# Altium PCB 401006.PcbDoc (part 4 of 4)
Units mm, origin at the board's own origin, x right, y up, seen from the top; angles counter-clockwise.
Board outline 117 x 63.5 mm, 4 copper layers (Top Layer, Mid-Layer 1, Mid-Layer 2, Bottom Layer), stack 1.68 mm thick; 205 components, 151 nets, 838 pads, 1570 vias.
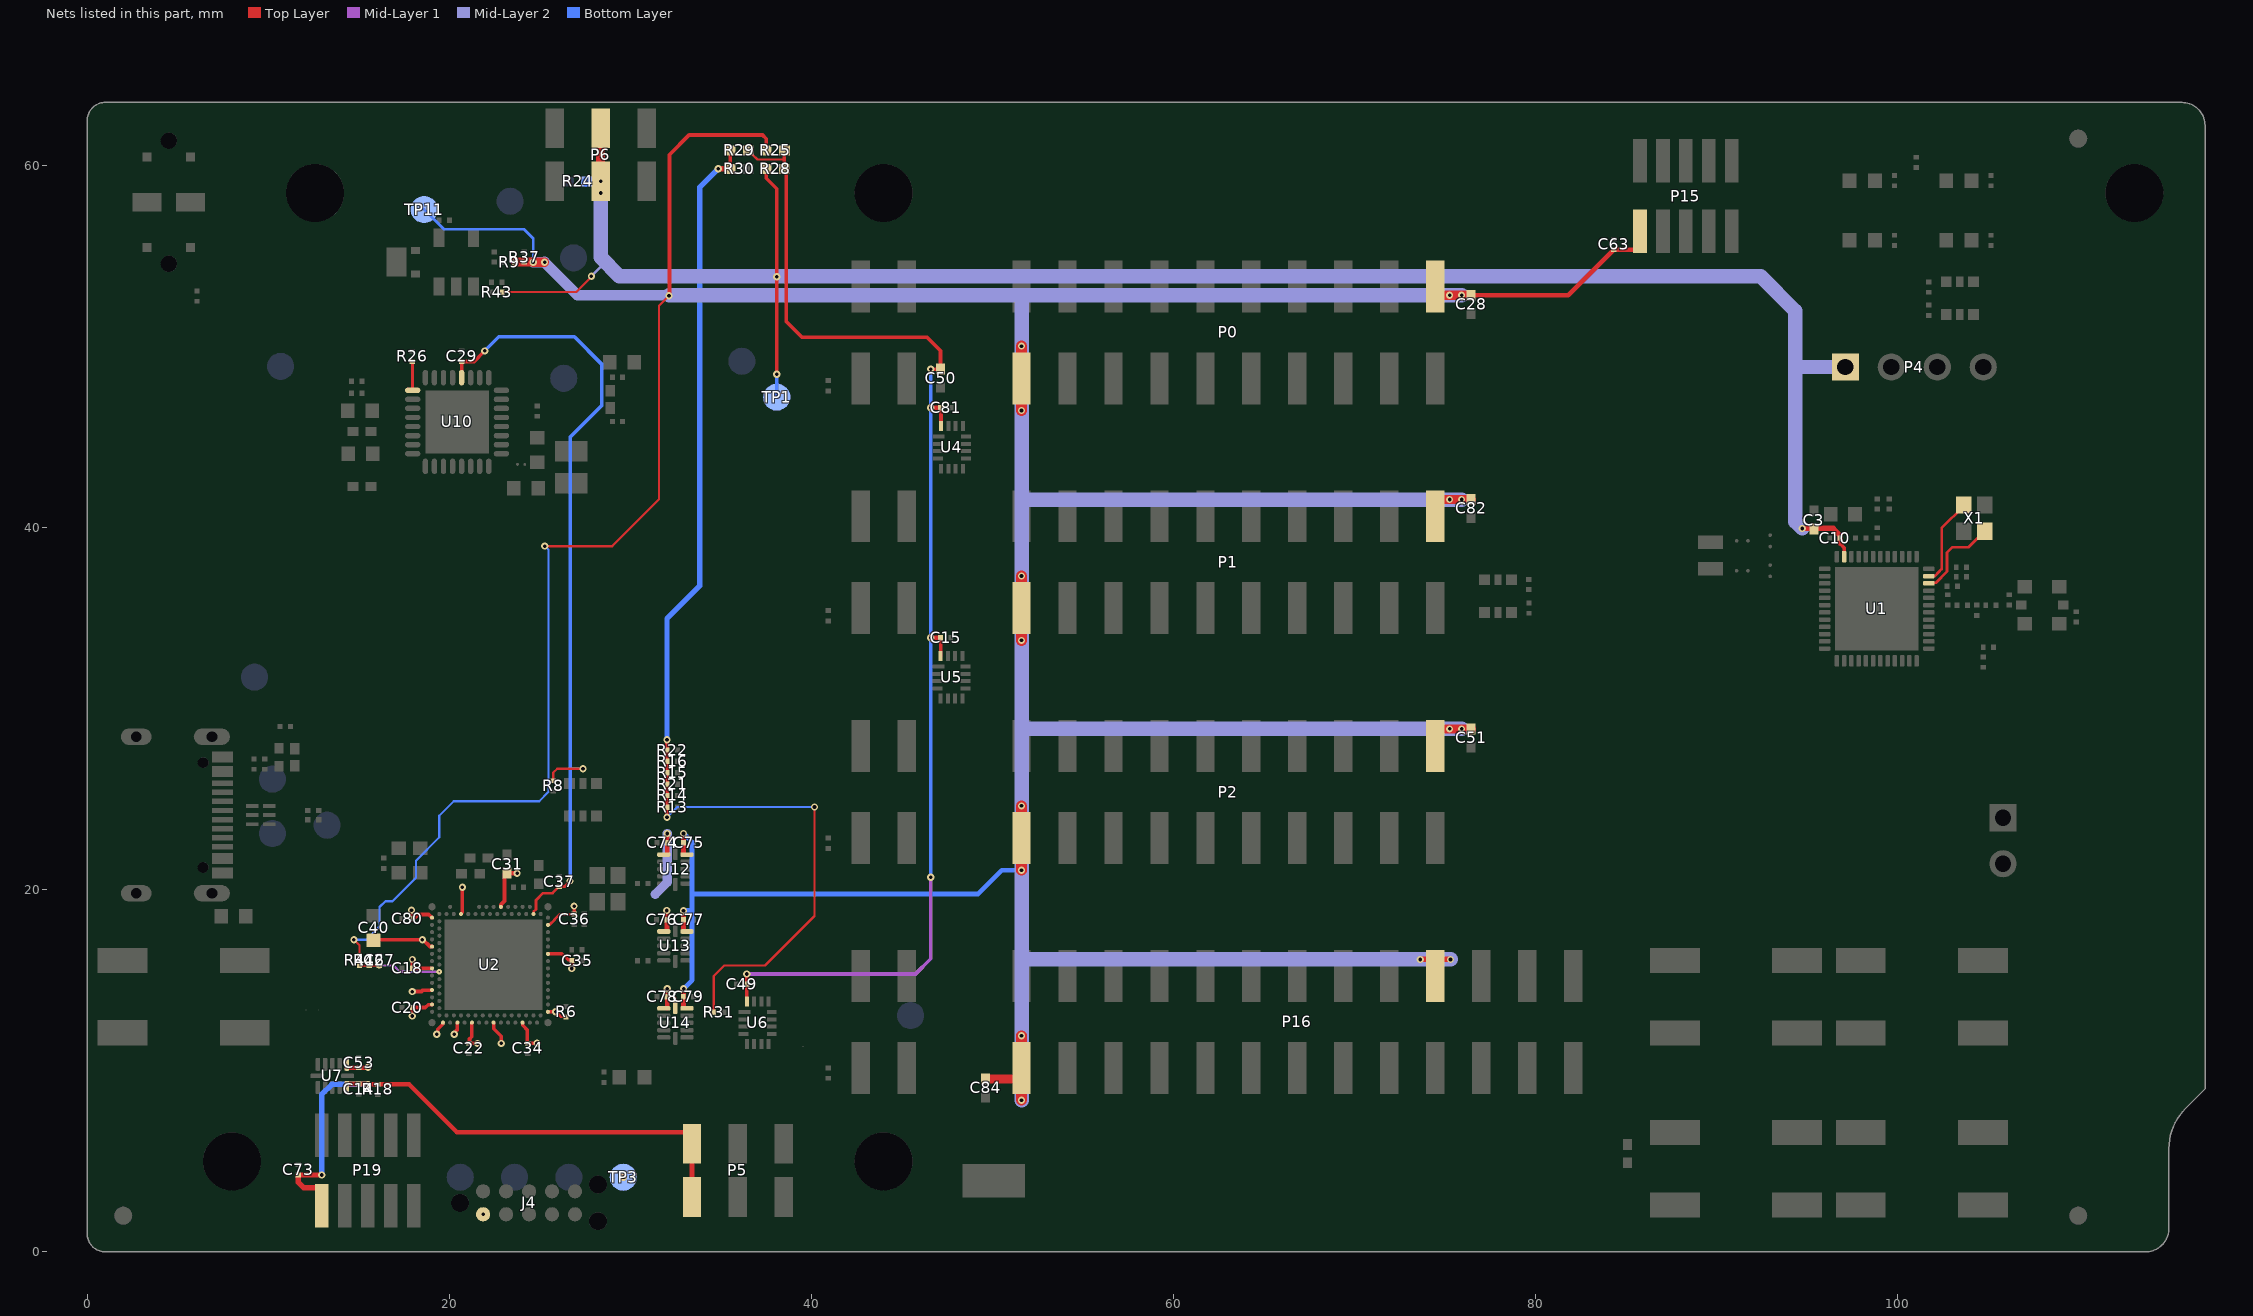
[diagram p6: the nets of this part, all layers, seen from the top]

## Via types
v1: diameter 0.4, hole 0.2, Top Layer to Bottom Layer, tented both sides, 1458 vias
v2: diameter 0.3, hole 0.1, Top Layer to Mid-Layer 1, tented top, 71 vias
v3: diameter 0.5, hole 0.25, Top Layer to Bottom Layer, tented both sides, 24 vias
v4: diameter 0.3, hole 0.1, Top Layer to Mid-Layer 1, tented both sides, 17 vias

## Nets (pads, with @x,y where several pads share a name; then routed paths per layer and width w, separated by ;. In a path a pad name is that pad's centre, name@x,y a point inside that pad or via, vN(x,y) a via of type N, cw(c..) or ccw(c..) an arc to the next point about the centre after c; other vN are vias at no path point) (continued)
VDD:DBGR: C18.1 C20.1 C22.1 C29.1 C31.1 C34.1 C35.1 C36.1 C37.1 C40.1 C53.2 C74.1 C76.1 C78.1 C80.1 J4.1 R6.2 R8.2 TP3.1 U2.A19 U2.AC1 U2.AG1 U2.AJ31 U2.AL3 U2.AL7 U2.AL11 U2.AL17 U2.AL25 U2.B8 U2.B28 U2.C1 U2.E31 U2.L1 U2.N31 U2.U1 U7.1 U10.12 U12.1 U13.1 U14.1 U14.12 | length 79.3
  Top Layer w0.125: R8.2@25.76,26.025 25.76,26.479 25.975,26.694 v1(27.4,26.694) ; C78.1@32.051,14.104 32.427,14.104 32.5,14.031 U14.12@32.5,13.5
  Top Layer w0.15: U2.B28@24.66,18.664 24.675,18.679 24.675,18.801 24.798,18.925 24.798,19.204 24.798,19.427 25.185,19.815 25.722,19.815 26.081,20.174 C37.1@26.096,20.174 26.11,20.188 26.383,20.188 v1(26.685,20.49) ; U2.E31@25.443,18.079 25.562,18.079 25.824,18.341 25.824,18.364 26.102,18.642 26.125,18.642 26.134,18.651 26.899,18.651 C36.1@26.909,18.661 ; v1(25.893,13.271) 26.173,12.991 26.454,12.991 R6.2@26.46,12.986
  Top Layer w0.187: U2.B8@20.66,18.664 20.66,18.675 20.735,18.75 v1(20.735,20.139) ; U2.N31@25.46,16.464 26.236,16.464 26.572,16.128 C35.1@26.691,16.128
  Top Layer w0.2: C40.1@16.018,17.25 v1(18.525,17.25) 18.562,17.25 18.943,16.869 19.055,16.869 U2.L1@19.06,16.864 ; v1(17.925,18.875) 17.949,18.851 17.949,18.426 C80.1@17.974,18.401 17.974,18.416 18.009,18.451 18.134,18.451 18.325,18.642 18.883,18.642 U2.C1@19.06,18.464 ; v1(17.968,13.03) 17.968,13.471 17.98,13.471 18.009,13.499 18.682,13.499 18.842,13.66 19.055,13.66 U2.AG1@19.06,13.664 ; v1(17.968,14.381) 17.976,14.388 18.481,14.388 18.558,14.464 U2.AC1@19.06,14.464 ; C18.1@17.974,15.63 v1@17.974,16.149 ; C18.1@17.979,15.664 U2.U1@19.06,15.664 ; v1(19.314,12.026) 19.372,12.083 19.372,12.296 19.655,12.58 19.655,12.66 U2.AL3@19.66,12.664 ; v1(20.279,12.026) 20.279,12.107 20.46,12.288 U2.AL7@20.46,12.664 ; U10.12@20.7,48.304 C29.1@20.7,49.19 21.39,49.19 v1(21.975,49.775) ; C22.1@21.092,11.524 21.127,11.559 21.13,11.559 21.13,11.759 21.26,11.889 U2.AL11@21.26,12.664 ; C22.1@21.101,11.521 21.572,11.521 v1(21.575,11.518) ; U2.AL17@22.46,12.664 22.46,12.334 22.878,11.916 v1(22.878,11.518) ; U2.AL25@24.06,12.664 24.065,12.66 24.065,12.514 24.318,12.261 24.318,11.549 C34.1@24.343,11.524 24.346,11.521 24.856,11.521 v1(24.86,11.525) ; U2.AJ31@25.46,13.264 25.887,13.264 v1(25.893,13.271) ; C35.1@26.691,16.128 26.748,16.128 26.783,16.093 C35.1@26.783,16.078 v1(26.782,15.659)
  Top Layer w0.203: v1(26.907,19.101) 26.909,19.1 C36.1@26.909,18.661
  Top Layer w0.225: U2.A19@22.86,19.064 22.86,19.179 23.073,19.392 23.073,20.848 C31.1@23.15,20.924 ; C31.1@23.2,20.916 v1(23.759,20.916)
  Top Layer w0.27: U7.1@14.362,10.174 C53.2@15.004,10.174 15.499,10.174 v1(15.525,10.2) ; U13.1@32.031,17.737 C76.1@32.031,18.354 v1(32.031,18.862) ; U14.1@32.051,13.462 32.051,14.104 v1(32.051,14.539) ; U12.1@32.051,21.987 C74.1@32.051,22.604 v1(32.051,23.112)
  Mid-Layer 1 w0.2: v1@21.541,11.484 v1(21.575,11.518) v1@21.632,11.461
  Mid-Layer 2 w0.508: 31.39,19.759 32.051,20.42 v1(32.051,23.112)
  Bottom Layer w0.125: 26.685,26.694 v1(27.4,26.694)
  Bottom Layer w0.2: v1(21.575,11.518) v1@21.656,11.518 ; v1(21.975,49.775) 22.75,50.55 26.925,50.55 28.425,49.05 28.425,46.739 26.685,44.999 26.685,26.694 v1(26.685,20.49)
  other v1: 21.878,2.074 29.62,4.125 17.975,16.15
VDD:IO: C28.2 C51.2 C63.2 C75.1 C77.1 C79.1 C82.2 C84.2 P0.1 P0.20 P1.1 P1.20 P2.1 P2.20 P15.1 P16.1 P16.20 R9.2 R25.1 R37.2 R41.2 TP11.1 U12.11 U13.11 U14.11 | length 311.3
  Top Layer w0.125: v1(14.742,17.25) 15.053,16.939 R41.2@15.053,16.384 ; v1(25.288,38.989) 29.014,38.989 31.598,41.572 31.598,52.273 v1(32.15,52.825)
  Top Layer w0.2: R37.2@24.142,54.675 R37.2@24.144,54.672 ; v1@24.647,54.672 v1(24.65,54.67) ; v1(32.15,52.825) 32.175,52.85 32.175,60.615 33.26,61.7 37.318,61.7 37.525,61.493 R25.1@37.525,60.85
  Top Layer w0.25: C28.2@76.466,52.845 81.821,52.845 C63.2@84.346,55.37 85.784,55.37 P15.1@85.784,56.38
  Top Layer w0.27: U14.11@32.948,13.514 32.952,14.104 v1(32.955,14.539) C79.1@32.948,14.104 ; U13.11@32.948,17.727 C77.1@32.948,18.344 v1(32.948,18.852) ; U12.11@32.948,21.987 C75.1@32.948,22.604 v1(32.948,23.112)
  Top Layer w0.305: v1(73.646,16.156) v1(75.322,16.156)
  Top Layer w0.5: R9.2@23.669,54.674 R37.2@24.142,54.675 24.645,54.674 v1@24.647,54.672 ; v1@24.652,54.672 v1(25.278,54.672)
  Top Layer w0.508: C84.2@49.643,9.556 51.37,9.556 51.624,9.81 P16.1@51.624,10.16 ; P2.20@74.484,27.94 74.484,28.639 74.738,28.893 v1(75.272,28.893) v1(75.934,28.893) C51.2@76.466,28.893 ; P1.20@74.484,40.64 74.484,41.314 74.738,41.568 v1(75.272,41.568) v1(75.934,41.568) C82.2@76.466,41.568 ; P0.20@74.484,53.34 74.484,53.099 74.738,52.845 v1(75.272,52.845) v1(75.934,52.845) C28.2@76.466,52.845
  Top Layer w0.6: v1(51.624,8.382) P16.1@51.624,9.81 ; P16.1@51.624,10.16 v1(51.624,11.938) ; v1(51.624,21.082) P2.1@51.624,22.86 v1(51.624,24.638) ; v1(51.624,33.782) P1.1@51.624,35.56 v1(51.624,37.338) ; v1(51.624,46.482) P0.1@51.624,48.26 v1(51.624,50.038)
  Mid-Layer 2 w0.6: v1(24.65,54.67) 24.652,54.672 v1(25.278,54.672) ; v1@25.275,54.675 v1(25.278,54.672) ; v1@32.125,52.85 27.1,52.85 v1(25.278,54.672)
  Mid-Layer 2 w0.8: v1@32.17,52.845 51.624,52.845 ; v1(51.624,8.382) 51.624,16.162 ; 51.65,28.905 75.272,28.905 v1@75.934,28.905 ; v1(75.322,16.156) v1(73.646,16.156) 51.631,16.156 51.624,16.162 ; v1@75.934,41.561 51.624,41.561 ; v1(75.934,52.845) v1(75.272,52.845) 51.624,52.845 ; 51.624,16.162 v1(51.624,24.638) 51.624,28.905 v1(51.624,33.782) v1(51.624,37.338) 51.624,41.561 ; 51.624,41.561 v1(51.624,46.482) v1(51.624,50.038) 51.624,52.845
  Bottom Layer w0.125: v1(14.742,17.25) 15.438,17.25 16.162,17.974 16.162,19.049 16.488,19.375 16.875,19.375 18.175,20.675 18.175,21.614 19.462,22.901 19.462,24.098 20.264,24.9 24.975,24.9 25.487,25.413 25.487,38.789 v1(25.288,38.989)
  Bottom Layer w0.15: TP11.1@18.622,57.582 19.704,56.5 24.127,56.5 24.65,55.977 v1(24.65,54.67)
  Bottom Layer w0.27: v1(32.948,18.852) 33.423,18.852 ; v1(32.948,23.112) 33.423,22.636 33.423,19.775 ; v1(32.955,14.539) 33.423,15.007 33.423,18.852 ; v1(51.624,21.082) 50.532,21.082 49.225,19.775 33.423,19.775 ; 33.423,18.852 33.423,19.775
VDD:nRF: C3.2 C10.1 P4.1 P6.2 R24.1 R28.1 R43.1 TP1.1 U1.47 | length 114.1
  Top Layer w0.125: R43.1@22.92,53.025 27.025,53.025 v1@27.894,53.894
  Top Layer w0.2: R28.1@37.519,59.83 37.519,59.31 38.104,58.725 v1(38.104,53.863) v1(38.104,48.489) ; 96.873,39.142 96.873,39.085 97.068,38.889 U1.47@97.068,38.555
  Top Layer w0.3: v1(28.372,58.493) v1(28.372,59.141) ; v1(94.756,39.966) 96.458,39.966 96.844,39.58 C10.1@96.844,39.438 96.844,39.17 96.873,39.142
  Top Layer w0.5: v1(28.372,59.141) P6.2@28.372,62.071
  Mid-Layer 2 w0.15: v1(27.862,53.9) 28.372,54.41 28.372,54.937
  Mid-Layer 2 w0.8: v1(28.372,59.141) v1(28.372,58.493) 28.372,54.937 29.409,53.9 31.65,53.9 ; 31.7,53.9 92.455,53.9 94.375,51.98 94.375,48.884 ; v1(94.756,39.966) 94.375,40.347 94.375,48.884 ; P4.1@97.134,48.884 94.375,48.884
  Bottom Layer w0.2: TP1.1@38.104,47.219 v1(38.104,48.489)
  Bottom Layer w0.55: R24.1@27.599,59.141 v1(28.372,59.141) v1(28.372,58.493)
VDD:SW: C15.1 C49.1 C50.2 C81.1 R25.2 R28.2 R29.2 U4.16 U5.16 U6.16 | length 70.4
  Top Layer w0.125: R29.2@36.525,60.85 36.55,60.85 36.762,60.637 36.762,60.612 37.034,60.341 38.519,60.341 ; R25.2@38.287,60.637 38.5,60.85 R25.2@38.525,60.85
  Top Layer w0.2: U6.16@36.45,13.825 C49.1@36.45,14.794 v1(36.45,15.35) ; R28.2@38.519,59.83 38.519,60.341 R25.2@38.519,60.836 ; R28.2@38.625,59.83 38.625,51.397 39.497,50.525 46.4,50.525 47.15,49.775 C50.2@47.15,48.769 v1(46.615,48.769) ; C15.1@47.154,33.917 47.16,33.911 U5.16@47.16,32.911 ; U4.16@47.178,45.612 C81.1@47.178,46.628
  Top Layer w0.254: v1(46.609,33.928) C15.1@47.143,33.928 ; v1(46.615,46.628) C81.1@47.148,46.628
  Mid-Layer 1 w0.2: v1(36.45,15.35) 45.766,15.35 46.615,16.199 v1(46.615,20.695)
  Bottom Layer w0.2: v1(46.615,20.695) v1(46.615,46.628) v1(46.615,48.769)
VDD:SW_PU: R13.1 R14.1 R15.1 R16.1 R21.1 R22.1 R29.1 R30.1 R31.1 | length 62
  Top Layer w0.125: R31.1@34.621,13.25 34.621,15.241 35.2,15.821 37.454,15.821 40.189,18.556 v1(40.189,24.575)
  Top Layer w0.2: v1(32.04,24.006) R13.1@32.04,24.575 R14.1@32.04,25.214 R15.1@32.04,26.47 R22.1@32.04,27.726 v1(32.04,28.295) ; R30.1@35.525,59.83 R29.1@35.525,60.85
  Top Layer w0.3: v1(34.865,59.83) R30.1@35.525,59.83
  Bottom Layer w0.125: v1(32.04,24.006) 32.609,24.575 v1(40.189,24.575)
  Bottom Layer w0.3: v1(32.04,28.295) 32.04,34.987 33.84,36.787 33.84,58.805 v1(34.865,59.83)
VDD:SWD0: C14.1 C73.2 P5.3 P19.1 R18.2 U7.11 | length 34.7
  Top Layer w0.15: v1(15.525,9.25) v1@15.531,9.256 ; R18.2@16.058,9.256 R18.2@16.064,9.262
  Top Layer w0.25: v1(15.525,9.25) 16.058,9.25 17.8,9.25 20.433,6.616 33.035,6.616 33.42,6.231 P5.3@33.42,3.035
  Top Layer w0.27: U7.11@14.411,9.275 14.414,9.277 C14.1@15.004,9.277 15.498,9.277 v1(15.525,9.25)
  Top Layer w0.3: P19.1@12.964,2.55 12.964,3.32 12.734,3.55 11.964,3.55 11.679,3.835 C73.2@11.679,4.246 v1(12.964,4.246)
  Bottom Layer w0.3: v1(12.964,4.246) 12.964,8.689 13.525,9.25 v1(15.525,9.25)
VMEAS_CH1: C67.1 R41.1 R42.2 U2.V2 | length 4.5
  Top Layer w0.125: R41.1@15.053,15.814 16.143,15.814 v2(16.145,15.815)
  Mid-Layer 1 w0.125: v2(16.145,15.815) 16.935,15.815 17.27,15.48 v2(19.46,15.48)
VSET1: R26.1 U10.17 | length 1.9
  Top Layer w0.15: U10.17@17.742,47.665 17.811,47.596 U10.17@17.992,47.596 17.974,47.614 R26.1@17.974,49.183
XC1: U1.34 X1.1 | length 4.9
  Top Layer w0.15: U1.34@101.698,36.93 101.735,36.967 102.138,36.967 102.755,37.583 102.755,38.63 103.055,38.93 103.951,38.93 X1.1@104.83,39.809
XC2: U1.35 X1.3 | length 5
  Top Layer w0.15: U1.35@101.698,37.33 U1.35@101.748,37.38 ; U1.35@101.748,37.33 102.075,37.33 102.293,37.549 102.293,37.552 102.455,37.714 102.455,39.984 103.68,41.209 X1.3@103.68,41.259
pads on no net: Fid1.0 Fid2.0 Fid3.0 H1. H2. H3. H4. H5. J3. J3.0 J3.A8 J3.B8 J4.0 J4.6 J4.7 J4.8 J4.9 P0.8 P0.9 P0.10 P0.11 P0.12 P0.13 P0.14 P0.15 P0.16 P0.17 P0.18 P5.2 P15.6 P15.7 P15.8 P16.21 P16.22 P16.23 P16.24 P16.25 P16.26 P17.3 P19.7 P19.8 P19.9 P30.3 P31.3 P32.3 SW4.0 SW4.1 SW4.6 U2. U2.A1 U2.A21 U2.A31 U2.AD2 U2.AE31 U2.AG31 U2.AH2 U2.AJ1 U2.AK2 U2.AK4 U2.AK6 U2.AK8 U2.AK10 U2.AK12 U2.AK14 U2.AK22 U2.AK24 U2.AK26 U2.AK28 U2.AK30 U2.AL1 U2.AL31 U2.B10 U2.B14 U2.D2 U2.F2 U2.J1 U2.K2 U2.M2 U2.P2 U2.T2 U2.W1 U2.Y2 U4.7 U4.12 U5.7 U5.12 U6.7 U6.12 U6.13 U6.14 U6.15 U10.5 U10.7 U10.9 U10.10 U10.11 U10.15 U10.18 U10.19 U10.25 U10.26 U10.27 U14.2 U14.10

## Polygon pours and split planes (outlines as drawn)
GND on Top Layer "Top_Layer-GND" (solid, remove dead copper, pour order 10): 0.002,0.009 0.002,63.509 117.004,63.509 117.004,0.009
P5V0 on Top Layer "P5V0" (solid, remove dead copper, pour order 0): 16.496,48.5 16.496,50.01 17.748,51.263 17.748,59.646 17.294,60.1 14.15,60.1 10.475,56.425 10.475,49.451 11.426,48.5
GND on Top Layer "GND_island" (solid, pour order 4): 103.874,35.423 103.874,34.914 104.306,34.482 104.991,34.482 105.397,34.888 105.397,35.422
GND on Mid-Layer 2 "Mid_Layer2-GND" (solid, remove dead copper, pour order 7): 0.029,0 0.029,63.5 117.004,63.5 117.004,0
VDD:DBGR on Mid-Layer 2 "VDD_DBGR" (solid, pour order 6): 21.754,1.825 25.2,1.825 26.025,2.65 29.176,2.65 30.011,3.485 30.011,4.789 28.85,5.95 28.85,10.719 32.51,14.379 32.51,19.319 30.379,21.45 19,21.45 17.725,20.175 17.725,14.809 15.02,12.104 15.02,10.019 21.219,3.821 21.219,2.36
GND on Mid-Layer 1 "Mid_Layer1-GND" (solid, remove dead copper, pour order 1): 0.029,0 0.029,63.22 117.004,63.22 117.004,0
GND on Bottom Layer "Bottom_Layer-GND" (solid, remove dead copper, pour order 3): 0.029,0 0.029,63.5 117.004,63.5 117.004,0

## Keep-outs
Top Layer:
  region: 112,26.473 cw(c112,29.973) 108.5,29.973 cw(c112,29.973) 112,33.473 cw(c112,29.973) 115.5,29.973 cw(c112,29.973)
  region: 108.496,6.473 cw(c108.496,9.973) 104.996,9.973 cw(c108.496,9.973) 108.496,13.473 cw(c108.496,9.973) 111.996,9.973 cw(c108.496,9.973)
  region: 42.496,14.473 cw(c42.496,17.973) 38.996,17.973 cw(c42.496,17.973) 42.496,21.473 cw(c42.496,17.973) 45.996,17.973 cw(c42.496,17.973)
  region: 74.996,0.473 cw(c74.996,3.973) 71.496,3.973 cw(c74.996,3.973) 74.996,7.473 cw(c74.996,3.973) 78.496,3.973 cw(c74.996,3.973)
  region: 3.496,-0.027 cw(c3.496,3.473) -0.004,3.473 cw(c3.496,3.473) 3.496,6.973 cw(c3.496,3.473) 6.996,3.473 cw(c3.496,3.473)
  region: 20.496,33.473 cw(c20.496,36.973) 16.996,36.973 cw(c20.496,36.973) 20.496,40.473 cw(c20.496,36.973) 23.996,36.973 cw(c20.496,36.973)
  region: 16.496,56.973 cw(c16.496,60.473) 12.996,60.473 cw(c16.496,60.473) 16.496,63.973 cw(c16.496,60.473) 19.996,60.473 cw(c16.496,60.473)
  region: 35.496,52.473 cw(c35.496,55.973) 31.996,55.973 cw(c35.496,55.973) 35.496,59.473 cw(c35.496,55.973) 38.996,55.973 cw(c35.496,55.973)
  region: 77.796,54.973 cw(c77.796,58.473) 74.296,58.473 cw(c77.796,58.473) 77.796,61.973 cw(c77.796,58.473) 81.296,58.473 cw(c77.796,58.473)
  region: 46.352,19.687 ccw(c49.352,19.687) 49.352,16.687 ccw(c49.352,19.687) 52.352,19.687 ccw(c49.352,19.687) 49.352,22.687 ccw(c49.352,19.687)
  region: 8.004,2 cw(c8.004,5) 5.004,5 cw(c8.004,5) 8.004,8 cw(c8.004,5) 11.004,5 cw(c8.004,5)
  region: 44.004,2 cw(c44.004,5) 41.004,5 cw(c44.004,5) 44.004,8 cw(c44.004,5) 47.004,5 cw(c44.004,5)
  region: 106.004,1.979 cw(c106.004,4.979) 103.004,4.979 cw(c106.004,4.979) 106.004,7.979 cw(c106.004,4.979) 109.004,4.979 cw(c106.004,4.979)
  region: 98.967,25.576 cw(c98.967,28.576) 95.967,28.576 cw(c98.967,28.576) 98.967,31.576 cw(c98.967,28.576) 101.967,28.576 cw(c98.967,28.576)
  region: 113.104,55.5 cw(c113.104,58.5) 110.104,58.5 cw(c113.104,58.5) 113.104,61.5 cw(c113.104,58.5) 116.104,58.5 cw(c113.104,58.5)
  region: 44.004,55.5 cw(c44.004,58.5) 41.004,58.5 cw(c44.004,58.5) 44.004,61.5 cw(c44.004,58.5) 47.004,58.5 cw(c44.004,58.5)
  region: 16.439,59.569 cw(c16.439,62.569) 13.439,62.569 cw(c16.439,62.569) 16.439,65.569 cw(c16.439,62.569) 19.439,62.569 cw(c16.439,62.569)
Keep-Out Layer:
  circle w0.152: c12.604,58.5 r2.4
  circle w0.152: c113.104,58.5 r2.4
  circle w0.152: c113.104,58.5 r2.4
  circle w0.152: c44.004,5 r2.4
  circle w0.152: c44.004,58.5 r2.4
  circle w0.152: c8.004,5 r2.4

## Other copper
Top Layer:
  rectangle net GND: 6.891,20.422 8.776,21.247
  rectangle net GND: 6.919,27.025 8.804,27.85
  rectangle net GND: 109.224,34.036 110.038,34.931
  rectangle net PCBANT: 115.025,16.986 116.295,17.748
  pour cut-out: 19.46,18.664 25.46,18.664 25.46,13.064 19.46,13.064
  pour cut-out: 18.4,47.9 22.5,47.9 22.5,43.8 18.4,43.8
  pour cut-out: 96.038,38.3 101.588,38.3 101.588,32.7 96.038,32.7
  pour cut-out: 59.075,26.354 57.866,26.354 57.866,26.875 59.075,26.875
  pour cut-out: 56.686,24.808 56.686,26.018 56.876,26.018 56.876,24.808
  pour cut-out: 54.821,29.737 57.983,29.737 57.983,29.216 54.821,29.216
  pour cut-out: 88.839,38.697 88.839,36.825 88.872,36.825 88.872,38.697
  region net RF: 106.555,35.98 106.35,35.865 106.35,35.595 106.555,35.48
  pour cut-out: 103.186,37.196 103.186,35.986 102.665,35.986 102.665,37.196
  pour cut-out: 103.615,35.429 103.615,34.92 104.047,34.488 104.733,34.488 105.139,34.894 105.139,34.895 105.139,35.429 105.289,35.429 105.289,34.808 104.807,34.326 103.968,34.326 103.46,34.834 103.46,35.429
  region net VBUS:IN1: 11.725,27.181 11.725,26.525 10.879,26.525 10.731,26.393 10.555,26.234 10.251,26.234 9.946,26.234 9.641,26.234 6.876,26.234 6.719,26.077 6.719,22.178 6.864,22.034 8.059,22.034 8.059,21.434 6.873,21.434 5.95,22.357 5.95,25.875 6.909,26.834 10.35,26.825 10.35,27.181
  region net ANT: 102.638,35.582 103.445,35.582 103.445,35.877 102.638,35.877 102.108,35.82 102.108,35.64
  region net ANT: 102.643,35.879 102.254,35.829 102.254,35.63 102.643,35.579
  pour cut-out: 105.668,42.014 105.668,38.93 102.8,38.93 102.8,42.014
  pour cut-out: 97.121,41.292 96.912,41.292 96.912,41.179 97.121,41.179
  pour cut-out: 99.353,39.615 98.54,39.615 98.54,40.962 99.353,40.962
  pour cut-out: 25.839,43.656 25.839,43.016 27.809,43.016 27.809,43.656
  region net PVSS1: 22.892,44.446 23.264,44.446 23.499,44.211 23.499,43.936 23.199,43.636 23.199,41.786 23.949,41.786 23.949,42.536 24.65,43.237 25.267,43.237 25.267,43.996 24.164,43.996 23.414,44.746 22.892,44.746
  region net P5V0: 15.382,45.946 15.382,48.629 17.367,48.629 17.367,46.334 17.454,46.246 18.042,46.246 18.042,45.946
  region net NetC27_2: 24.549,42.586 25.69,42.586 25.817,42.713 25.817,43.016 27.652,43.016 27.652,41.589 27.474,41.411 24.549,41.411
  region net P5V0: 23.603,45.459 24.467,44.596 25.267,44.596 25.267,46.296 24.167,46.296 23.603,45.733
  region net NetC59_1: 7.89,19.8 7.89,18.1 5.902,18.1 5.902,19.8
Mid-Layer 1:
  pour cut-out: 110.038,37.125 106.927,37.125 106.048,36.247 106.048,35.204 106.927,34.325 110.038,34.325
  pour cut-out: 103.459,35.509 103.459,34.834 103.967,34.326 104.806,34.326 105.288,34.808 105.288,35.509
  pour cut-out: 12.225,12.775 12.225,13.975 12.717,13.975 12.717,12.775
Mid-Layer 2:
  pour cut-out: 110.038,37.125 106.927,37.125 106.048,36.247 106.048,35.204 106.927,34.325 110.038,34.325
  pour cut-out: 103.459,35.509 103.459,34.834 103.967,34.326 104.806,34.326 105.288,34.808 105.288,35.509
  region net P5V0: 25.168,45.289 25.278,45.415 25.278,46.113 22.766,48.625 16.8,48.625 16.8,47.005 16.93,46.875 18.454,46.875 19.029,47.45 21.896,47.45 22.125,47.221 22.125,45.396 22.233,45.287
Bottom Layer:
  pour cut-out: 19.572,57.582 cw(c18.62,57.582) 18.62,56.63 cw(c18.62,57.578) 17.672,57.578 17.672,57.589 cw(c18.613,57.589) 18.613,58.53 18.623,58.53 cw(c18.623,57.582)
  pour cut-out: 16.397,44.858 cw(c15.446,44.858) 15.446,43.906 cw(c15.446,44.854) 14.498,44.854 14.498,44.865 cw(c15.439,44.865) 15.439,45.806 15.449,45.806 cw(c15.449,44.858)
  pour cut-out: 20.072,29.999 cw(c19.12,29.999) 19.12,29.047 cw(c19.12,29.995) 18.172,29.995 18.172,30.006 cw(c19.113,30.006) 19.113,30.947 19.124,30.947 cw(c19.124,29.999)
  pour cut-out: 10.085,12.152 cw(c9.133,12.152) 9.133,11.2 cw(c9.133,12.149) 8.185,12.149 8.185,12.159 cw(c9.126,12.159) 9.126,13.1 9.137,13.1 cw(c9.137,12.152)
  pour cut-out: 23.027,54.815 cw(c22.075,54.815) 22.075,53.863 cw(c22.075,54.811) 21.127,54.811 21.127,54.822 cw(c22.068,54.822) 22.068,55.763 22.079,55.763 cw(c22.079,54.815)
  pour cut-out: 15.483,54.307 cw(c14.531,54.307) 14.531,53.355 cw(c14.531,54.303) 13.583,54.303 13.583,54.314 cw(c14.524,54.314) 14.524,55.255 14.535,55.255 cw(c14.535,54.307)
  pour cut-out: 32.984,37.568 cw(c32.032,37.568) 32.032,36.617 cw(c32.032,37.565) 31.084,37.565 31.084,37.576 cw(c32.025,37.576) 32.025,38.517 32.036,38.517 cw(c32.036,37.568)
  pour cut-out: 38.368,38.713 cw(c37.417,38.713) 37.417,37.761 cw(c37.417,38.71) 36.469,38.71 36.469,38.72 cw(c37.41,38.72) 37.41,39.661 37.42,39.661 cw(c37.42,38.713)
  pour cut-out: 39.869,42.397 cw(c38.918,42.397) 38.918,41.445 cw(c38.918,42.393) 37.969,42.393 37.969,42.404 cw(c38.91,42.404) 38.91,43.345 38.921,43.345 cw(c38.921,42.397)
  pour cut-out: 27.284,48.262 cw(c26.332,48.262) 26.332,47.31 cw(c26.332,48.258) 25.384,48.258 25.384,48.269 cw(c26.325,48.269) 26.325,49.21 26.336,49.21 cw(c26.336,48.262)
  pour cut-out: 14.213,38.847 cw(c13.261,38.847) 13.261,37.895 cw(c13.261,38.843) 12.313,38.843 12.313,38.854 cw(c13.254,38.854) 13.254,39.795 13.265,39.795 cw(c13.265,38.847)
  pour cut-out: 11.19,41.354 cw(c10.239,41.354) 10.239,40.403 cw(c10.239,41.351) 9.291,41.351 9.291,41.362 cw(c10.232,41.362) 10.232,42.303 10.242,42.303 cw(c10.242,41.354)
  pour cut-out: 11.19,38.354 cw(c10.239,38.354) 10.239,37.403 cw(c10.239,38.351) 9.291,38.351 9.291,38.362 cw(c10.232,38.362) 10.232,39.303 10.242,39.303 cw(c10.242,38.354)
  pour cut-out: 16.982,27.612 cw(c16.03,27.612) 16.03,26.66 cw(c16.03,27.608) 15.082,27.608 15.082,27.619 cw(c16.023,27.619) 16.023,28.56 16.034,28.56 cw(c16.034,27.612)
  pour cut-out: 22.747,27.434 cw(c21.796,27.434) 21.796,26.482 cw(c21.796,27.43) 20.848,27.43 20.848,27.441 cw(c21.789,27.441) 21.789,28.382 21.799,28.382 cw(c21.799,27.434)
  pour cut-out: 25.747,28.424 cw(c24.796,28.424) 24.796,27.473 cw(c24.796,28.421) 23.848,28.421 23.848,28.432 cw(c24.789,28.432) 24.789,29.373 24.799,29.373 cw(c24.799,28.424)
  pour cut-out: 28.747,28.424 cw(c27.796,28.424) 27.796,27.473 cw(c27.796,28.421) 26.848,28.421 26.848,28.432 cw(c27.789,28.432) 27.789,29.373 27.799,29.373 cw(c27.799,28.424)
  pour cut-out: 38.165,26.748 cw(c37.213,26.748) 37.213,25.796 cw(c37.213,26.744) 36.265,26.744 36.265,26.755 cw(c37.206,26.755) 37.206,27.696 37.217,27.696 cw(c37.217,26.748)
  pour cut-out: 38.165,21.748 cw(c37.213,21.748) 37.213,20.796 cw(c37.213,21.744) 36.265,21.744 36.265,21.755 cw(c37.206,21.755) 37.206,22.696 37.217,22.696 cw(c37.217,21.748)
  pour cut-out: 38.165,16.748 cw(c37.213,16.748) 37.213,15.796 cw(c37.213,16.744) 36.265,16.744 36.265,16.755 cw(c37.206,16.755) 37.206,17.696 37.217,17.696 cw(c37.217,16.748)
  pour cut-out: 38.965,11.748 cw(c38.013,11.748) 38.013,10.796 cw(c38.013,11.744) 37.065,11.744 37.065,11.755 cw(c38.006,11.755) 38.006,12.696 38.017,12.696 cw(c38.017,11.748)
  pour cut-out: 60.633,22.631 60.074,22.631 60.074,23.114 60.633,23.114
  pour cut-out: 60.712,25.966 59.639,25.966 59.639,26.015 60.712,26.015
  pour cut-out: 61.576,13.266 60.649,13.266 60.649,13.315 61.576,13.315
  pour cut-out: 59.29,24.948 58.141,24.948 58.141,24.996 59.29,24.996
  pour cut-out: 59.055,20.734 56.388,20.734 56.388,20.782 59.055,20.782
  pour cut-out: 54.712,19.131 54.153,19.131 54.153,19.614 54.712,19.614
  pour cut-out: 54.155,12.242 54.155,13.169 54.204,13.169 54.204,12.242
  pour cut-out: 68.37,18.138 69.298,18.138 69.298,18.09 68.37,18.09
  pour cut-out: 69.85,25.507 69.926,25.481 69.545,24.897 69.494,24.948
  pour cut-out: 67.434,25.847 68.085,25.847 68.085,25.799 67.434,25.799
  pour cut-out: 64.977,21.14 65.485,21.14 65.485,21.038 64.977,21.038
Multi-Layer:
  pour cut-out: 110.035,0.028 117.023,0.028 116.971,63.5 110.041,63.5

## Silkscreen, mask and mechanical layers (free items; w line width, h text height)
Top Overlay:
  circle w0.15: c27.1,57.087 r0.884
  region: 29.212,56.075 28.512,55.183 27.837,56.075
  region: 24.975,55.203 25.675,56.095 26.35,55.203
  lines w0.15: 15.875,41.75 15.875,40.767 29.075,40.767 29.075,45.4 ; 15.875,47.175 15.875,50.261 29.07,50.261 29.07,49.85 ; 15.879,15.3 15.879,11.244 20.675,11.244 ; 15.879,19.375 15.879,23.05 29.077,23.05 29.078,21.596 ; 21.539,11.244 23.851,11.244 ; 24.841,11.244 29.078,11.244 ; 29.075,11.244 29.075,18.447 ; 30.15,56.35 31.65,56.35 ; 30.45,56.1 31.35,56.1 ; 30.7,55.855 31.1,55.855 ; 30.9,56.35 30.9,57.1 ; 42.179,17.075 42.179,17.575 42.424,17.575 ; 42.204,29.8 42.204,30.3 42.45,30.3 ; 42.204,42.5 42.204,43 42.45,43 ; 42.204,55.2 42.204,55.7 42.45,55.7 ; 45.533,17.575 45.779,17.575 45.779,17.075 ; 45.559,30.3 45.804,30.3 45.804,29.8 ; 45.559,43 45.804,43 45.804,42.5 ; 45.559,55.7 45.804,55.7 45.804,55.2 ; 105.875,35.1 105.875,31.1 94,31.1 94,39.125 94,42.125 101.489,42.125 105.875,42.125 105.875,36.725
  lines w0.178: 25.668,56.32 25.668,56.5 ; 25.668,56.785 25.668,57.098 25.925,57.098 ; 28.275,57.1 28.525,57.1 28.525,56.787 ; 28.525,56.308 28.525,56.489
  text "ON" at 0.35,61.3 h1.4
  text "LED0" at 96.062,59.727 h1.8
  text "LED1" at 101.887,59.727 h1.8
  text "GPIO pins shown in parentheses are only available on headers with modification" at 50.325,59.25 h1.6
  text "VDD / CURRENT / MEASURE" at 16.649,58.208 h1.8
  text "A" at 26.65,56.65 h1.52
  text "LED2" at 96.087,56.427 h1.8
  text "LED3" at 101.887,56.427 h1.8
  text "VDD / IO" at 72.368,55.255 h1.52
  text "GND" at 42.63,55.215 h1.52
  text "GND" at 50.165,55.209 h1.52
  text "01" at 53.565,55.209 h1.52
  text "03" at 55.965,55.209 h1.52
  text "POWER" at 8.575,54.488 h1.8 r90
  text "OFF" at 0.35,53.425 h1.4
  text "DEBUG IN" at 84.426,53.054 h1.8
  text "IDD" at 26.125,52.9 h1.52 r90
  text "GND" at 31.375,52.125 h1.52 r90
  text "nRF54" at 28.925,51.4 h1.52 r90
  text "PMIC" at 15.81,50.281 h1.8
  text "PORT0" at 50.023,46.838 h1.8 r90
  text "00" at 53.487,45.475 h1.52
  text "02" at 56.008,45.47 h1.52
  text "04" at 58.548,45.47 h1.52
  text "GND" at 73.162,45.475 h1.52
  text "P5V0" at 41.187,45.458 h1.52
  text "VDD / IO" at 49.227,44.352 h1.52
  text "GND" at 42.63,42.515 h1.52
  text "09" at 63.687,42.5 h1.52
  text "11" at 66.562,42.5 h1.52
  text "13" at 68.962,42.5 h1.52
  text "15" at 71.452,42.5 h1.52
  text "GND" at 50.19,42.493 h1.52
  text "03" at 56.019,42.493 h1.52
  text "05" at 58.523,42.493 h1.52
  text "07" at 61.063,42.493 h1.52
  text "VDD / IO" at 72.417,42.488 h1.52
  text "(01)" at 53.25,42.25 h1.52
  text "nRF54LS05" at 93.93,42.15 h1.8
  text ".PCBNumber" at 0.584,38.811 h2.03
  text ".PCBRevision" at 0.598,37.381 h1.78
  text "PORT1" at 50.023,34.138 h1.8 r90
  text "nRF54LS05-DK" at 0.515,33.45 h3
  text "02" at 56.069,32.72 h1.52
  text "04" at 58.548,32.72 h1.52
  text "06" at 61.088,32.72 h1.52
  text "08" at 63.628,32.72 h1.52
  text "10" at 66.345,32.72 h1.52
  text "12" at 68.937,32.725 h1.52
  text "14" at 71.425,32.72 h1.52
  text "GND" at 73.129,32.73 h1.52
  text "P5V0" at 41.187,32.707 h1.52
  text "(00)" at 53.075,32.45 h1.52
  text "VDD / IO" at 49.227,31.583 h1.52
  text "27" at 66.265,29.846 h1.52
  text "29" at 68.725,29.846 h1.52
  text "GND" at 50.19,29.826 h1.52
  text "17" at 53.659,29.826 h1.52
  text "19" at 56.159,29.826 h1.52
  text "21" at 58.699,29.826 h1.52
  text "23" at 61.135,29.835 h1.52
  text "25" at 63.636,29.835 h1.52
  text "31" at 71.225,29.836 h1.52
  text "GND" at 42.63,29.815 h1.52
  text "VDD / IO" at 72.392,29.724 h1.52
  text "DEBUGGER" at 0.587,29.149 h1.8
  text "DEBUGGER" at 15.813,23.05 h1.8
  text "PORT1" at 50.023,21.438 h1.8 r90
  text "P5V0" at 41.187,20.069 h1.52
  text "16" at 53.675,20.076 h1.52
  text "18" at 56.175,20.069 h1.52
  text "20" at 58.557,20.069 h1.52
  text "22" at 61.223,20.079 h1.52
  text "24" at 63.768,20.079 h1.52
  text "26" at 66.353,20.069 h1.52
  text "28" at 68.897,20.069 h1.52
  text "30" at 71.361,20.069 h1.52
  text "GND" at 73.275,20.025 h1.52
  text "VDD / IO" at 49.227,18.941 h1.52
  text "BUTTON 0" at 87.075,17.323 h1.8
  text "BUTTON 1" at 97.325,17.323 h1.8
  text "D1" at 61.094,17.097 h1.52
  text "E1" at 63.595,17.097 h1.52
  text "F1" at 68.837,17.097 h1.52
  text "GND" at 42.604,17.089 h1.52
  text "B0" at 53.411,17.084 h1.52
  text "D3" at 66.107,17.084 h1.52
  text "GND" at 50.176,17.065 h1.52
  text "C1" at 55.978,17.065 h1.52
  text "C3" at 58.467,17.065 h1.52
  text "G0" at 71.07,17.065 h1.52
  text "VDD / IO" at 72.336,17.047 h1.52
  text "RESET" at 1.397,9.242 h1.8
  text "EXPAN" at 50.023,8.738 h1.8 r90
  text "BUTTON 2" at 87.075,7.822 h1.8
  text "BUTTON 3" at 97.336,7.822 h1.8
  text "GND" at 38.975,7.7 h1.52 r90
  text "P5V0" at 41.187,7.409 h1.52
  text "A0" at 53.348,7.372 h1.52
  text "C0" at 55.891,7.372 h1.52
  text "C2" at 58.48,7.372 h1.52
  text "D0" at 60.99,7.372 h1.52
  text "E0" at 63.59,7.372 h1.52
  text "D2" at 66.119,7.372 h1.52
  text "F0" at 68.17,7.372 h1.52
  text "C4" at 71.145,7.372 h1.52
  text "GND" at 73.063,7.372 h1.52
  text "VDD / SWD0" at 35,7.206 h1.52 r90
  text "VDD / IO" at 49.608,6.252 h1.52
  text "GND" at 47.918,1.425 h1.4
  text "DEBUG OUT" at 3.35,1.325 h1.8
  text "3.6V Max" at 13.05,0.325 h1.4
Bottom Overlay:
  drawing of 285 lines, arcs and shapes, not listed
  text "nRF54" at 41.782,41.441 h2.03 r180
  text "P1.30" at 27.013,39.145 h1.91 r180
  text "SWDCLK" at 32.746,39.126 h1.91 r180
  text "P1.29" at 27.013,36.617 h1.91 r180
  text "SWDIO" at 33.493,36.576 h1.91 r180
  text "DEBUGGER" at 42.334,35.375 h1.4 r180
  text "RESET" at 34.15,33.976 h1.91 r180
  text "BUTTON 3" at 87.597,33.156 h1.91 r180
  text "P0.04" at 82.331,32.511 h1.91 r180
  text "P1.07" at 27.013,31.521 h1.91 r180
  text "CTS1" at 34.501,31.527 h1.91 r180
  text "BUTTON 2" at 87.623,30.486 h1.91 r180
  text "P1.08" at 82.331,29.811 h1.91 r180
  text "P1.06" at 27.013,28.981 h1.91 r180
  text "RTS1" at 34.594,28.987 h1.91 r180
  text "nRF54" at 41.829,28.413 h2.03 r180
  text "BUTTON 1" at 87.623,27.781 h1.91 r180
  text "P1.09" at 82.327,27.134 h1.91 r180
  text "P1.04" at 27.013,26.441 h1.91 r180
  text "TXD1" at 34.359,26.442 h1.91 r180
  text "GPIO" at 96.048,25.636 h1.78 r180
  text "BUTTON 0" at 87.59,25.13 h1.91 r180
  text "PIN" at 41.681,24.413 h1.78 r180
  text "P1.13" at 82.331,24.411 h1.91 r180
  text "P1.05" at 27.013,23.901 h1.91 r180
  text "RXD1" at 34.347,23.902 h1.91 r180
  text "SB6" at 66.343,21.797 h1.91 r180
  text "P0.03" at 82.327,21.749 h1.91 r180
  text "LED 3" at 89.058,21.736 h1.91 r180
  text "P1.16" at 27.013,21.363 h1.91 r180
  text "CTS0" at 34.234,21.368 h1.91 r180
  text "P1.01" at 52.373,20.411 h1.91 r180
  text "XL2" at 59.892,20.389 h1.91 r180
  text "1M" at 97.086,20.172 h1.52 r180
  text "GPIO" at 73.074,19.375 h1.78 r180
  text "SB4" at 66.343,19.105 h1.91 r180
  text "P0.02" at 82.327,19.057 h1.91 r180
  text "LED 2" at 89.058,19.057 h1.91 r180
  text "P1.15" at 27.013,18.823 h1.91 r180
  text "RTS0" at 34.326,18.828 h1.91 r180
  text "GPIO" at 96.057,17.523 h1.78 r180
  text "DEBUGGER" at 42.379,16.9 h1.4 r180
  text "SB5" at 66.343,16.413 h1.91 r180
  text "P0.01" at 82.327,16.364 h1.91 r180
  text "LED 1" at 89.058,16.341 h1.91 r180
  text "P1.10" at 27.013,16.283 h1.91 r180
  text "TXD0" at 34.091,16.272 h1.91 r180
  text "P1.00" at 52.373,15.026 h1.91 r180
  text "XL1" at 59.993,15.004 h1.91 r180
  text "PIN" at 78.434,14.827 h1.78 r180
  text "LED 0" at 89.07,14.474 h1.91 r180
  text "P1.14" at 27.013,13.755 h1.91 r180
  text "RXD0" at 34.079,13.732 h1.91 r180
  text "SB3" at 66.343,13.72 h1.91 r180
  text "P0.00" at 82.327,13.672 h1.91 r180
  text "P5V0" at 100.398,13.25 h1.52 r180
  text "GPIO" at 51.916,11.631 h1.99 r180
  text "Function" at 57.408,11.631 h1.99 r180
  text "Short" at 66.394,11.631 h1.99 r180
  text "HW" at 74.979,11.606 h1.99 r180
  text "GPIO" at 81.904,11.584 h1.99 r180
  text "Function" at 87.375,11.584 h1.99 r180
  text "HW" at 97.853,11.569 h1.99 r180
  text "GPIO" at 27.016,11.191 h2.03 r180
  text "Function" at 32.899,11.188 h2.03 r180
  text "Circuit" at 43.32,11.182 h2.03 r180
Board Outline:
  the board outline again, w0.254
PCB Info:
  circle w0.013: c113.104,58.5 r3
  circle w0.013: c113.104,58.5 r3
  circle w0.013: c113.104,58.5 r3
  circle w0.013: c113.104,58.5 r3
  circle w0.013: c113.104,58.5 r3
  circle w0.013: c113.104,58.5 r3
  circle w0.013: c98.969,28.576 r3
  circle w0.013: c98.969,28.576 r3
  circle w0.013: c98.969,28.576 r3
  circle w0.013: c98.969,28.576 r3
  circle w0.013: c98.969,28.576 r3
  circle w0.013: c98.969,28.576 r3
  circle w0.013: c106.004,5 r3
  circle w0.013: c106.004,5 r3
  circle w0.013: c106.004,5 r3
  circle w0.013: c106.004,5 r3
  circle w0.013: c106.004,5 r3
  circle w0.013: c106.004,5 r3
  circle w0.013: c44.004,5 r3
  circle w0.013: c44.004,5 r3
  circle w0.013: c44.004,5 r3
  circle w0.013: c44.004,5 r3
  circle w0.013: c44.004,5 r3
  circle w0.013: c44.004,5 r3
  circle w0.013: c49.35,19.687 r3
  circle w0.013: c49.35,19.687 r3
  circle w0.013: c49.35,19.687 r3
  circle w0.013: c49.35,19.687 r3
  circle w0.013: c49.35,19.687 r3
  circle w0.013: c49.35,19.687 r3
  circle w0.013: c8.004,5 r3
  circle w0.013: c8.004,5 r3
  circle w0.013: c8.004,5 r3
  circle w0.013: c8.004,5 r3
  circle w0.013: c8.004,5 r3
  circle w0.013: c8.004,5 r3
  circle w0.013: c16.425,62.569 r3
  circle w0.013: c16.425,62.569 r3
  circle w0.013: c16.425,62.569 r3
  circle w0.013: c16.425,62.569 r3
  circle w0.013: c16.425,62.569 r3
  circle w0.013: c16.425,62.569 r3
  circle w0.013: c44.004,58.5 r3
  circle w0.013: c44.004,58.5 r3
  circle w0.013: c44.004,58.5 r3
  circle w0.013: c44.004,58.5 r3
  circle w0.013: c44.004,58.5 r3
  circle w0.013: c44.004,58.5 r3
  circle w0.013: c112,29.973 r3.5
  circle w0.013: c112,29.973 r3.5
  circle w0.013: c112,29.973 r3.5
  circle w0.013: c112,29.973 r3.5
  circle w0.013: c35.496,55.973 r3.5
  circle w0.013: c35.496,55.973 r3.5
  circle w0.013: c3.496,3.473 r3.5
  circle w0.013: c3.496,3.473 r3.5
  circle w0.013: c74.996,3.973 r3.5
  circle w0.013: c74.996,3.973 r3.5
  circle w0.013: c108.496,9.973 r3.5
  circle w0.013: c108.496,9.973 r3.5
  circle w0.013: c77.796,58.473 r3.5
  circle w0.013: c77.796,58.473 r3.5
  circle w0.013: c42.496,17.973 r3.5
  circle w0.013: c42.496,17.973 r3.5
  circle w0.013: c20.496,36.973 r3.5
  circle w0.013: c20.496,36.973 r3.5
  circle w0.013: c74.996,3.973 r3.5
  circle w0.013: c74.996,3.973 r3.5
  circle w0.013: c16.496,60.473 r3.5
  circle w0.013: c16.496,60.473 r3.5
  circle w0.013: c42.496,17.973 r3.5
  circle w0.013: c42.496,17.973 r3.5
  circle w0.013: c16.496,60.473 r3.5
  circle w0.013: c16.496,60.473 r3.5
  circle w0.013: c35.496,55.973 r3.5
  circle w0.013: c35.496,55.973 r3.5
  circle w0.013: c20.496,36.973 r3.5
  circle w0.013: c20.496,36.973 r3.5
  circle w0.013: c108.496,9.973 r3.5
  circle w0.013: c108.496,9.973 r3.5
  circle w0.013: c3.496,3.473 r3.5
  circle w0.013: c3.496,3.473 r3.5
  circle w0.013: c77.796,58.473 r3.5
  circle w0.013: c77.796,58.473 r3.5
  circle w0.013: c42.496,17.973 r3.5
  circle w0.013: c42.496,17.973 r3.5
  circle w0.013: c20.496,36.973 r3.5
  circle w0.013: c20.496,36.973 r3.5
  circle w0.013: c112,29.973 r3.5
  circle w0.013: c112,29.973 r3.5
  circle w0.013: c35.496,55.973 r3.5
  circle w0.013: c35.496,55.973 r3.5
  circle w0.013: c16.496,60.473 r3.5
  circle w0.013: c16.496,60.473 r3.5
  circle w0.013: c108.496,9.973 r3.5
  circle w0.013: c108.496,9.973 r3.5
  circle w0.013: c77.796,58.473 r3.5
  circle w0.013: c77.796,58.473 r3.5
  circle w0.013: c3.496,3.473 r3.5
  circle w0.013: c3.496,3.473 r3.5
  circle w0.013: c74.996,3.973 r3.5
  circle w0.013: c74.996,3.973 r3.5
  lines w0.1: 85.074,59.435 85.074,62.57 107.451,62.57 107.451,59.435 85.074,59.435
  text "PCB manufacturer code to be placed on Bottom Layer inside this frame" at 106.756,62.179 h1.4 r180
Top Assembly:
  lines w0.1: 9.15,23.502 10.08,23.502 10.08,24.775 9.15,24.775 9.15,23.502
  text "D1" at 9.385,23.936 h0.31
Top Impedance Info:
  lines w0.153: 7.485,23.384 8.174,23.384 ccw(c8.174,23.873) 8.519,23.528 cw(c8.776,23.271) 8.776,23.634 9.135,23.634 ; 7.49,24.884 8.127,24.884 cw(c8.127,24.318) 8.527,24.718 ccw(c8.73,24.921) 8.73,24.634 9.135,24.634 ; 10.065,23.634 10.567,23.634 ccw(c10.567,24.104) 10.899,23.772 cw(c11.408,23.263) 11.408,23.982 12.101,23.982 cw(c12.101,23.884) 12.2,23.884 ; 10.065,24.634 10.567,24.634 cw(c10.567,24.164) 10.899,24.496 ccw(c11.408,25.005) 11.408,24.285 12.101,24.285 ccw(c12.101,24.384) 12.2,24.384 ; 12.8,23.884 cw(c12.898,23.884) 12.898,23.982 13.925,23.982 cw(c13.925,23.158) 14.75,23.158 14.75,21.422 ccw(c16.6,21.422) 16.6,19.572 19.033,19.572 cw(c19.033,19.138) 19.467,19.138 19.467,18.664 ; 12.8,24.384 ccw(c12.898,24.384) 12.898,24.285 13.925,24.285 cw(c13.925,23.158) 15.053,23.158 15.053,21.422 ccw(c16.6,21.422) 16.6,19.875 19.033,19.875 cw(c19.033,19.138) 19.77,19.138 19.77,18.755 ccw(c19.86,18.755) 19.86,18.664
  text "90-ohms grounded coplanar differential" at 7.452,25.664 h0.64
Bottom Placement:
  circle w0.15: c19.122,29.997 r0.95
  circle w0.15: c38.919,42.395 r0.95
  circle w0.15: c26.334,48.26 r0.95
  circle w0.15: c15.447,44.856 r0.95
  circle w0.15: c23.62,4.115 r0.95
  circle w0.15: c20.62,4.115 r0.95
  circle w0.15: c26.62,4.115 r0.95
  circle w0.15: c29.62,4.115 r0.95
  circle w0.15: c16.004,2 r0.95
  circle w0.15: c9.135,12.15 r0.95
  circle w0.15: c10.24,23.113 r0.95
  circle w0.15: c10.24,26.115 r0.95
  circle w0.15: c13.263,23.571 r0.95
  circle w0.15: c16.032,27.61 r0.95
  circle w0.15: c21.797,27.432 r0.95
  circle w0.15: c24.797,28.423 r0.95
  circle w0.15: c27.797,28.423 r0.95
  circle w0.15: c37.215,26.746 r0.95
  circle w0.15: c37.215,21.746 r0.95
  circle w0.15: c37.215,16.746 r0.95
  circle w0.15: c37.215,11.746 r0.95
  circle w0.15: c45.496,13.056 r0.95
  circle w0.15: c9.25,31.75 r0.95
  circle w0.15: c10.24,38.353 r0.95
  circle w0.15: c10.24,41.353 r0.95
  circle w0.15: c13.263,38.845 r0.95
  circle w0.15: c32.034,37.567 r0.95
  circle w0.15: c37.418,38.711 r0.95
  circle w0.15: c38.104,47.219 r0.95
  circle w0.15: c36.174,49.2 r0.95
  circle w0.15: c10.698,48.92 r0.95
  circle w0.15: c14.533,54.305 r0.95
  circle w0.15: c18.622,57.582 r0.95
  circle w0.15: c22.077,54.813 r0.95
  circle w0.15: c26.877,54.915 r0.95
  circle w0.15: c23.372,58.039 r0.95
  text "Circles mark PCA10145 v0.9.0 test point locations" at 9.793,61.805 h0.6

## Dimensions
0.029,63.5 to 12.6,58.5 on Dimension
0,0 to 8.004,5 on Dimension
0,63.856 to 12.6,58.5 on Dimension
0,0 to 8,5 on Dimension
113.104,58.5 to 106.004,5 on Dimension
44.004,5 to 106.004,5 on Dimension
8.004,5 to 44.004,5 on Dimension
44.004,58.5 to 113.104,58.5 on Dimension
12.604,58.5 to 44.004,58.5 on Dimension
0,0 to 0,63.5 on Dimension
0,0 to 117.004,0 on Dimension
